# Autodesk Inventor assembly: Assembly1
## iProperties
Author: Jan
Created: 2002-05
Part Number: Assembly1
Document SubType Name: Assembly
Designer: Jan
Control State: 0
Master: False
Checked Out: False
PropertySet Name: Design Tracking Control
Shininess: 64.0
Angle Display Precision: 2
Document Length Units: 11269
Document Angle Units: 11283
Document Time Units: 11279
Document Mass Units: 11290
Document Length Units Precision: 3
Document Angle Units Precision: 2
Compacted: False
PropertySet Name: _Private Model Information
Density: 0.0
Volumn: 0.0
Area: 0.0
PropertySet Name: Model Information
